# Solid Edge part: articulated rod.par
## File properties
Author: Deepak Maini
Template: Normal.par
Last saved by: Robert a Rhodes jr
Revision: 7
Application: Solid Edge
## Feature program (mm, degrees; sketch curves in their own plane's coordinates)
sketch for "unnamed Protrusion 1" plane through (0, 0, 0) normal (0, -1, 0) x-axis (1, 0, 0)
  line (-89, 9) -> (-89, -9)
  line (-89, -9) -> (89, -9)
  line (89, -9) -> (89, 9)
  line (89, 9) -> (-89, 9)
extrude "unnamed Protrusion 1" add finite 18 symmetric
sketch for "unnamed Protrusion 2" plane through (0, 0, 0) normal (0, 0, 1) x-axis (1, 0, 0)
  circle centre (89, 0) radius 17.5
extrude "unnamed Protrusion 2" add finite 42 symmetric
sketch for "unnamed Hole 1" plane through (89, 0, 21) normal (0, 0, 1) x-axis (1, 0, 0)
  hole centre (0, 0) bore radius 12
hole "unnamed Hole 1" through
sketch for "unnamed Protrusion 3" plane through (0, 0, 0) normal (0, 0, 1) x-axis (1, 0, 0)
  circle centre (-89, 0) radius 12
extrude "unnamed Protrusion 3" add finite 28 symmetric
sketch for "unnamed Hole 2" plane through (-89, 0, 14) normal (0, 0, 1) x-axis (1, 0, 0)
  hole centre (0, 0) bore radius 7.5
hole "unnamed Hole 2" through
fillet "unnamed Round 1"
sketch for "unnamed Cutout 1" plane through (-2.9078, 0, 9) normal (0, 0, 1) x-axis (1, 0, 0)
  line (-64.0922, 6.35) -> (65.9078, 6.35)
  arc centre (-64.0922, 0) radius 6.35 from (-64.0922, -6.35) to (-64.0922, 6.35) cw
  line (-64.0922, -6.35) -> (65.9078, -6.35)
  arc centre (65.9078, 0) radius 6.35 from (65.9078, 6.35) to (65.9078, -6.35) cw
  dimension (linear) = 64.0922
extrude "unnamed Cutout 1" cut finite 6.5 along -normal
mirror "unnamed Mirror 1" of "unnamed Cutout 1"
pattern "unnamed Pattern 1"
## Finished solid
Body 1: solid body, 26 faces, 56 edges, 32 vertices.
  Faces by surface: plane 14, cylinder 12
  Edges by curve: circle 28, line 28
Bounding box of the edges (mm): 207.500 x 35.000 x 42.000, from (-101, -17.5, -21) to (106.5, 17.5, 21).
Cylindrical faces by radius (mm): R6.35 x4, R7.5 x1, R12 x2, R17.5 x1, R24 x4
Planar faces by outward normal: +y 3, +z 4, -y 3, -z 4
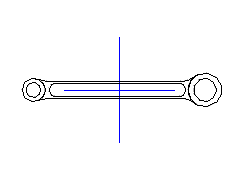
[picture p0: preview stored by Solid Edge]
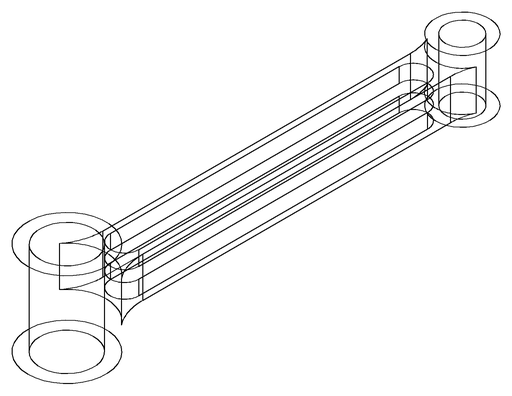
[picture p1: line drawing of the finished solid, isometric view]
